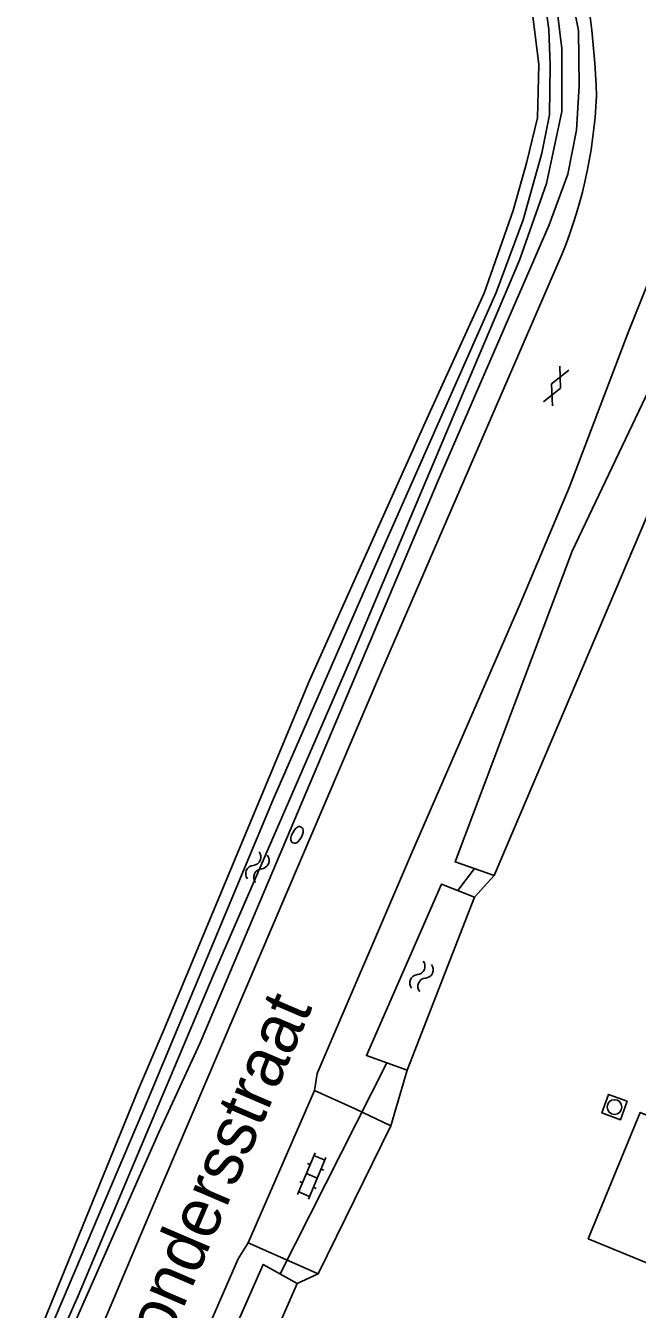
# Model space of a CAD drawing. Extents: x 133000 to 136000, y 400500 to 403500.
# Drawn here: x 134512.8 to 134543.9, y 400587.4 to 400652.6 of the extents above; entities that cross this region are included whole.
import ezdxf

# ---------------------------------------------------------------- set-up
doc = ezdxf.new("R2010")
doc.units = 0
for name, color, linetype in [('gg-anno-openbare ruimte label', 7, 'Continuous'), ('gg-bbg-hoofdgebouw', 7, 'Continuous'), ('gg-knt-verharding', 7, 'Continuous'), ('gg-kntw-bovenkant insteek waterloop', 7, 'Continuous'), ('gg-kntw-waterlijn', 7, 'Continuous'), ('gg-kwrk-duiker nz buis', 7, 'Continuous'), ('gt-grn-groengrens', 7, 'Continuous'), ('gt-symb-brandkraan', 7, 'Continuous'), ('gt-symb-gesloten verharding', 7, 'Continuous'), ('gt-symb-klinker verharding', 7, 'Continuous'), ('gt-symb-rioolschacht', 7, 'Continuous'), ('gt-symb-watersymbool', 7, 'Continuous')]:
    doc.layers.add(name, color=color, linetype=linetype)

# ---------------------------------------------------------------- blocks, each defined once
blk = doc.blocks.new('gt0-WA')
at = {"layer": 'gt-symb-watersymbool'}
for centre, start, end in [((-0.323, 0.022), 28.07249, 151.92751), ((0.427, 0.422), 208.07248, 331.92751), ((-0.323, -0.428), 28.07249, 151.92751), ((0.427, -0.028), 208.07248, 331.92751)]:
    blk.add_arc(centre, 0.425, start, end, dxfattribs=at)
blk = doc.blocks.new('gt0-BR')
at = {"layer": 'gt-symb-brandkraan'}
for centre, radius, start, end in [((-0.244, 0), 0.206, 107.56694, 252.43307), ((0.599, -2.664), 3, 106.89205, 107.56694), ((0, -0.691), 0.938, 73.10799, 106.89205), ((-0.599, -2.664), 3, 72.43309, 73.10799), ((0.244, 0), 0.206, 287.56695, 72.43309), ((0.599, 2.664), 3, 252.43307, 253.10797), ((0, 0.691), 0.938, 253.10797, 286.89206), ((-0.599, 2.664), 3, 286.89206, 287.56695)]:
    blk.add_arc(centre, radius, start, end, dxfattribs=at)
blk = doc.blocks.new('gt0-GESVH1')
at = {"layer": 'gt-symb-gesloten verharding'}
for p, q in [((-0.992, -0.261), (0.008, 0.239)), ((0.008, -0.261), (-0.992, 0.239)), ((0.008, 0.239), (1.008, -0.261)), ((1.008, 0.239), (0.008, -0.261))]:
    blk.add_line(p, q, dxfattribs=at)
blk = doc.blocks.new('gt0-RS')
at = {"layer": 'gt-symb-rioolschacht'}
blk.add_lwpolyline([(-0.5, -0.5), (0.5, -0.5), (0.5, 0.5), (-0.5, 0.5)], close=True, dxfattribs=at)
blk.add_circle((0, 0), 0.375, dxfattribs=at)
blk = doc.blocks.new('gt0-KL1')
at = {"layer": 'gt-symb-klinker verharding'}
for p, q in [((-1.15, 0.3), (1.15, 0.3)), ((-1, -0.3), (-1, 0.3)), ((-0.5, 0.3), (-0.5, 0.45)), ((0, -0.3), (0, 0.3)), ((0.5, 0.3), (0.5, 0.45)), ((1, -0.3), (1, 0.3)), ((-1.15, -0.3), (1.15, -0.3)), ((-0.5, -0.45), (-0.5, -0.3)), ((0.5, -0.45), (0.5, -0.3))]:
    blk.add_line(p, q, dxfattribs=at)

msp = doc.modelspace()

# ---------------------------------------------------------------- linework, layer by layer
at = {"layer": 'gg-bbg-hoofdgebouw'}
msp.add_lwpolyline([(134544.368, 400589.716), (134541.363, 400590.949), (134543.998, 400597.369), (134546.995, 400596.132), (134547.09, 400596.361)], dxfattribs=at)
at = {"layer": 'gg-knt-verharding'}
for p, q in [((134546.925, 400645.89), (134543.392, 400636.987)), ((134527.452, 400598.486), (134524.09, 400590.739)), ((134527.452, 400598.486), (134529.528, 400597.543)), ((134531.337, 400596.691), (134529.528, 400597.543)), ((134527.644, 400589.176), (134531.337, 400596.691)), ((134524.09, 400590.739), (134524.089, 400590.737)), ((134524.089, 400590.737), (134527.644, 400589.176))]:
    msp.add_line(p, q, dxfattribs=at)
for points in [[(134515.125, 400582.867), (134519.165, 400592.406), (134530.804, 400619.678), (134539.813, 400640.467)], [(134543.392, 400636.987), (134540.409, 400629.137), (134537.898, 400623.193), (134532.38, 400610.518), (134527.592, 400599.341), (134527.452, 400598.486)], [(134524.089, 400590.737), (134523.575, 400589.927), (134520.595, 400583.092), (134520.557, 400582.999)]]:
    msp.add_lwpolyline(points, dxfattribs=at)
for centre, radius, start, end in [((134504.197, 400648.02), 37.591, 1.48445, 15.09233), ((134518.073, 400649.961), 23.723, 336.40822, 357.66341)]:
    msp.add_arc(centre, radius, start, end, dxfattribs=at)
at = {"layer": 'gg-kntw-bovenkant insteek waterloop'}
for p, q in [((134532.167, 400599.519), (134535.579, 400608.297)), ((134512.785, 400584.515), (134518.517, 400598.546)), ((134524.473, 400583.889), (134526.569, 400588.676))]:
    msp.add_line(p, q, dxfattribs=at)
for points in [[(134518.517, 400598.546), (134519.774, 400601.474), (134527.209, 400619.306), (134533.157, 400632.589), (134536.071, 400638.983), (134537.543, 400643.181), (134538.245, 400645.657), (134538.786, 400647.89), (134538.845, 400650.592), (134538.505, 400653.311), (134538.016, 400656.086), (134537.026, 400660.083), (134529.128, 400682.745)], [(134529.128, 400682.745), (134530.943, 400683.022), (134533.518, 400676.105), (134535.075, 400671.284), (134536.338, 400667.826), (134538.755, 400660.716), (134539.593, 400657.927), (134540.412, 400654.638), (134540.869, 400652.315), (134540.905, 400649.509), (134540.764, 400647.26), (134540.323, 400645.024), (134539.367, 400642.458), (134533.731, 400629.462), (134521.654, 400600.898)], [(134578.014, 400640.64), (134578.673, 400642.066), (134566.482, 400649.022), (134563.784, 400650.433), (134561.32, 400651.435), (134558.784, 400651.888), (134556.424, 400651.733), (134554.443, 400651.062), (134553.428, 400649.501), (134552.022, 400646.953), (134550.21, 400644.271), (134547.83, 400641.162), (134540.549, 400625.879), (134534.599, 400610.09), (134536.575, 400609.408)], [(134536.575, 400609.408), (134549.474, 400639.691), (134550.32, 400641.021), (134551.697, 400640.152), (134553.95, 400638.909), (134556.258, 400637.763), (134558.586, 400637.118), (134561.173, 400636.663), (134563.663, 400636.311), (134565.661, 400636.18), (134567.794, 400636.895), (134568.801, 400638.257), (134569.68, 400640.175), (134570.113, 400642.211), (134570.138, 400644.261), (134578.014, 400640.64)], [(134535.579, 400608.297), (134533.903, 400608.966), (134530.093, 400600.254), (134532.167, 400599.519)], [(134521.654, 400600.898), (134519.53, 400596.322), (134514.081, 400583.976), (134512.785, 400584.515)], [(134526.569, 400588.676), (134524.855, 400589.647), (134522.657, 400584.684)]]:
    msp.add_lwpolyline(points, dxfattribs=at)
at = {"layer": 'gg-kntw-waterlijn'}
msp.add_lwpolyline([(134539, 400654.966), (134539.361, 400652.378), (134539.434, 400650.561), (134539.398, 400648.033), (134539.001, 400646.095), (134538.062, 400642.711), (134536.69, 400639.016), (134530.79, 400625.698), (134525.36, 400613.257), (134519.022, 400598.099), (134513.387, 400584.842), (134513.92, 400584.616), (134515.457, 400588.055), (134518.014, 400594.125), (134522.308, 400604.317), (134529.279, 400620.366), (134534.826, 400633.48), (134537.862, 400640.659), (134539.247, 400644.545), (134540.015, 400648.21), (134540.027, 400651.412), (134539.573, 400655.018)], dxfattribs=at)
at = {"layer": 'gg-kwrk-duiker nz buis'}
for p, q in [((134534.741, 400608.632), (134535.587, 400609.749)), ((134525.712, 400589.162), (134531.13, 400599.886))]:
    msp.add_line(p, q, dxfattribs=at)
at = {"layer": 'gt-grn-groengrens'}
for p, q in [((134535.579, 400608.297), (134536.575, 400609.408)), ((134531.337, 400596.691), (134532.167, 400599.519)), ((134526.569, 400588.676), (134527.644, 400589.176))]:
    msp.add_line(p, q, dxfattribs=at)

# ---------------------------------------------------------------- block references
at = {"layer": 'gt-symb-brandkraan', "rotation": -117.33407585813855}
msp.add_blockref('gt0-BR', (134526.569, 400611.463), dxfattribs=at)
at = {"layer": 'gt-symb-gesloten verharding', "rotation": 65.48492926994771}
msp.add_blockref('gt0-GESVH1', (134539.715, 400634.262), dxfattribs=at)
at = {"layer": 'gt-symb-klinker verharding', "rotation": -112.76972663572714}
msp.add_blockref('gt0-KL1', (134527.318, 400594.142), dxfattribs=at)
at = {"layer": 'gt-symb-rioolschacht', "rotation": 159.9336503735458}
msp.add_blockref('gt0-RS', (134542.694, 400597.639), dxfattribs=at)
at = {"layer": 'gt-symb-watersymbool'}
for p, rotation in [((134524.531, 400609.78), 66.74124066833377), ((134532.865, 400604.233), 66.74124066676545)]:
    msp.add_blockref('gt0-WA', p, dxfattribs=dict(at, rotation=rotation))

# ---------------------------------------------------------------- texts
at = {"layer": 'gg-anno-openbare ruimte label'}
msp.add_text('Pater Dondersstraat', height=2.5, rotation=66.8, dxfattribs=at).set_placement((134515.569, 400575.216))

doc.saveas('drawing.dxf')
